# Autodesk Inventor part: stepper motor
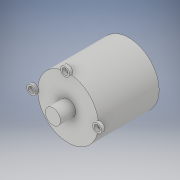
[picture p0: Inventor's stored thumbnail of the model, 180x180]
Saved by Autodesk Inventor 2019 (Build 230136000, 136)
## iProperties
Created: 2019-10
Part Number: stepper motor
Material: Generic
Document SubType Name: Sheet Metal
Designer: Lenovo
Density: 1 g/cm^3
Sheet Metal Rule: Default_mm
Appearance: Default
Author: Lenovo
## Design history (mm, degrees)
sketch "Sketch1"
  geometry: C1 r 10 at (0, 0); 1 further point
  constraints: 1 centre point, 1 coincident
  dimensions: "d0" = 20 diameter of C1
extrude "Extrusion1" new body sketch "Sketch1" distance "d1" = 20; taper "d2" = 0 deg
sketch "Sketch2"
  geometry: C1 r 2.5 at (0, 0); 1 further point
  constraints: 1 centre point, 1 coincident
  dimensions: "d3" = 5 diameter of C1
extrude "Extrusion2" join sketch "Sketch2" distance "d4" = 5; taper "d5" = 0 deg
sketch "Sketch3"
  geometry: C1 r 1.5 at (0, 10.845); C2 r 1 at (0, 10.845); 1 further point
  constraints: 2 centre point, 1 coincident
  dimensions: "d6" = 3 diameter of C1; "d7" = 2 diameter of C2
extrude "Extrusion3" join sketch "Sketch3" distance "d8" = 1; taper "d9" = 0 deg
sketch "Sketch4"
  geometry: C1 r 1.5 at (-11.127, 0); C2 r 1 at (-11.127, 0); 1 further point
  constraints: 2 centre point, 1 coincident
  dimensions: "d10" = 3 diameter of C1; "d11" = 2 diameter of C2
extrude "Extrusion4" join sketch "Sketch4" distance "d12" = 1; taper "d13" = 0 deg
sketch "Sketch5"
  geometry: C1 r 1.5 at (10.577, 0); C2 r 1 at (10.577, 0); 1 further point
  constraints: 2 centre point, 1 coincident
  dimensions: "d14" = 3 diameter of C1; "d15" = 2 diameter of C2
extrude "Extrusion5" join sketch "Sketch5" distance "d16" = 1; taper "d17" = 0 deg
sketch "Sketch6"
  geometry: 1 further point
body "Solid1"
other parameters: "Thickness" = 0.5, "BendRadius" = 0.5 (= Thickness), "BendReliefWidth" = 0.5 (= Thickness), "BendReliefDepth" = 0.25 (= 0.5 x Thickness), "CornerReliefSize" = 2 (= 4 x Thickness), "SeamGap" = 0.01, "MinimumRemnant" = 1 (= 2 x Thickness), "TransitionRadius" = 0.5 (= BendRadius), "JacobiRadiusSize" = 0.5 (= BendRadius), "GapSize" = 0.5 (= Thickness)
